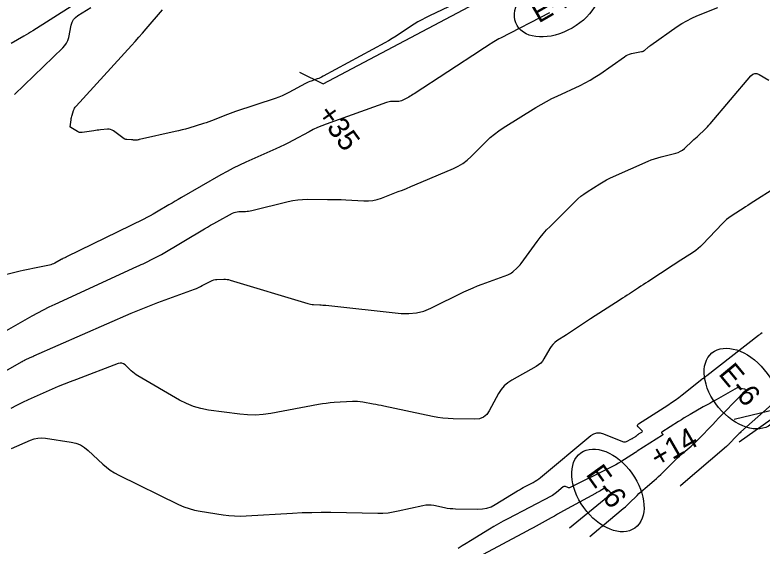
# Model space of a CAD drawing. Extents: x 1005228 to 1008882, y 1883389 to 1885754.
# Drawn here: x 1007873.1 to 1008093.9, y 1884195.8 to 1884352.9 of the extents above; entities that cross this region are included whole.
import ezdxf

# ---------------------------------------------------------------- set-up
doc = ezdxf.new("R2010")
doc.units = 0
for name, color, linetype in [('C-ANNO-NOTE', 7, 'Continuous'), ('R_Erosion', 7, 'Continuous'), ('S_BASELINE', 7, 'Continuous'), ('S_BRIDGE', 7, 'Continuous'), ('TSOBSTACLE', 7, 'Continuous')]:
    doc.layers.add(name, color=color, linetype=linetype)

msp = doc.modelspace()

# ---------------------------------------------------------------- linework, layer by layer
at = {"layer": 'C-ANNO-NOTE'}
for points in [[(1007870.6, 1884259.56), (1007878.17, 1884263.86), (1007879.85, 1884264.79), (1007881.54, 1884265.68), (1007883.26, 1884266.54), (1007885, 1884267.36), (1007909.17, 1884278.46), (1007909.78, 1884278.74), (1007910.38, 1884279.03), (1007910.99, 1884279.32), (1007911.6, 1884279.61), (1007914.01, 1884280.8), (1007914.61, 1884281.1), (1007915.21, 1884281.41), (1007915.79, 1884281.74), (1007916.38, 1884282.07), (1007929.12, 1884289.63), (1007930.02, 1884290.16), (1007930.93, 1884290.68), (1007931.85, 1884291.2), (1007932.77, 1884291.7), (1007937.45, 1884294.23), (1007937.88, 1884294.44), (1007938.33, 1884294.59), (1007938.79, 1884294.68), (1007939.27, 1884294.73), (1007941.21, 1884294.79), (1007941.7, 1884294.81), (1007942.18, 1884294.87), (1007942.65, 1884294.94), (1007943.13, 1884295.05), (1007953.84, 1884297.69), (1007955.25, 1884297.99), (1007956.67, 1884298.2), (1007958.1, 1884298.33), (1007959.54, 1884298.37), (1007965.52, 1884298.34), (1007966.86, 1884298.33), (1007968.2, 1884298.3), (1007969.54, 1884298.25), (1007970.88, 1884298.18), (1007976.26, 1884297.88), (1007977.58, 1884297.88), (1007978.87, 1884298.01), (1007980.15, 1884298.28), (1007981.4, 1884298.69), (1007986.37, 1884300.61), (1007987.61, 1884301.1), (1007988.85, 1884301.59), (1007990.08, 1884302.1), (1007991.31, 1884302.61), (1008002.73, 1884307.46), (1008004.15, 1884308.15), (1008005.5, 1884308.96), (1008006.75, 1884309.9), (1008007.93, 1884310.97), (1008012.44, 1884315.5), (1008013.6, 1884316.59), (1008014.82, 1884317.61), (1008016.09, 1884318.57), (1008017.42, 1884319.45), (1008027.1, 1884325.48), (1008028.64, 1884326.4), (1008030.2, 1884327.28), (1008031.79, 1884328.11), (1008033.41, 1884328.89), (1008040.13, 1884332.02), (1008041.63, 1884332.77), (1008043.1, 1884333.57), (1008044.54, 1884334.44), (1008045.93, 1884335.38), (1008053.22, 1884340.51), (1008053.72, 1884340.82), (1008054.24, 1884341.08), (1008054.78, 1884341.28), (1008055.35, 1884341.42), (1008058.29, 1884342.01), (1008058.56, 1884342.08), (1008058.81, 1884342.18), (1008059.05, 1884342.32), (1008059.27, 1884342.48), (1008060.12, 1884343.21), (1008060.34, 1884343.39), (1008060.56, 1884343.56), (1008060.78, 1884343.73), (1008061.01, 1884343.9), (1008068.86, 1884349.41), (1008070.24, 1884350.33), (1008071.68, 1884351.16), (1008073.15, 1884351.91), (1008074.68, 1884352.58), (1008080.85, 1884355.09)], [(1007889.7, 1884355.35), (1007878.37, 1884348.2), (1007877.72, 1884347.79), (1007877.06, 1884347.39), (1007876.4, 1884347), (1007875.74, 1884346.61), (1007871.97, 1884344.44)], [(1007873.01, 1884329.34), (1007887.28, 1884343.1), (1007887.89, 1884343.78), (1007888.38, 1884344.52), (1007888.75, 1884345.33), (1007889, 1884346.21), (1007889.75, 1884349.85), (1007890.02, 1884350.71), (1007890.43, 1884351.47), (1007890.99, 1884352.12), (1007891.7, 1884352.67), (1007895.53, 1884355.08)], [(1008031.07, 1884353.45), (1008016.57, 1884346.02), (1008016.09, 1884345.77), (1008015.61, 1884345.5), (1008015.13, 1884345.22), (1008014.66, 1884344.94), (1008012.8, 1884343.77), (1008012.34, 1884343.47), (1008011.88, 1884343.18), (1008011.42, 1884342.88), (1008010.96, 1884342.58), (1007991.1, 1884329.54), (1007990.7, 1884329.29), (1007990.3, 1884329.05), (1007989.89, 1884328.81), (1007989.48, 1884328.59), (1007987.71, 1884327.66), (1007987.34, 1884327.49), (1007986.96, 1884327.37), (1007986.56, 1884327.29), (1007986.16, 1884327.26), (1007984.5, 1884327.24), (1007984.09, 1884327.22), (1007983.69, 1884327.16), (1007983.29, 1884327.07), (1007982.9, 1884326.95), (1007965.09, 1884320.57), (1007963.8, 1884320.08), (1007962.53, 1884319.54), (1007961.29, 1884318.96), (1007960.06, 1884318.33), (1007955.19, 1884315.71), (1007953.97, 1884315.06), (1007952.74, 1884314.44), (1007951.49, 1884313.84), (1007950.24, 1884313.27), (1007941.38, 1884309.31), (1007939.5, 1884308.44), (1007937.63, 1884307.52), (1007935.8, 1884306.56), (1007933.98, 1884305.55), (1007922.3, 1884298.85), (1007921.37, 1884298.32), (1007920.45, 1884297.78), (1007919.53, 1884297.24), (1007918.6, 1884296.7), (1007914.92, 1884294.52), (1007914, 1884293.98), (1007913.06, 1884293.46), (1007912.12, 1884292.96), (1007911.16, 1884292.48), (1007888.35, 1884281.31), (1007888.21, 1884281.25), (1007888.08, 1884281.18), (1007887.95, 1884281.12), (1007887.81, 1884281.06), (1007887.28, 1884280.81), (1007887.15, 1884280.75), (1007887.01, 1884280.68), (1007886.88, 1884280.61), (1007886.76, 1884280.54), (1007884.87, 1884279.47), (1007884.51, 1884279.28), (1007884.13, 1884279.13), (1007883.75, 1884279), (1007883.35, 1884278.91), (1007878.42, 1884277.93), (1007877.46, 1884277.74), (1007876.51, 1884277.53), (1007875.56, 1884277.32), (1007874.61, 1884277.09), (1007861.08, 1884273.79)], [(1007852.9, 1884237.72), (1007875.23, 1884250.39), (1007875.31, 1884250.43), (1007875.38, 1884250.48), (1007875.46, 1884250.52), (1007875.54, 1884250.56), (1007875.85, 1884250.74), (1007875.93, 1884250.78), (1007876, 1884250.82), (1007876.08, 1884250.86), (1007876.16, 1884250.9), (1007877.6, 1884251.56), (1007877.87, 1884251.68), (1007878.13, 1884251.8), (1007878.4, 1884251.92), (1007878.67, 1884252.04), (1007907.49, 1884264.66), (1007909.45, 1884265.5), (1007911.41, 1884266.31), (1007913.39, 1884267.08), (1007915.38, 1884267.83), (1007926.15, 1884271.78), (1007926.75, 1884272.01), (1007927.33, 1884272.26), (1007927.9, 1884272.53), (1007928.47, 1884272.82), (1007930.96, 1884274.17), (1007931.4, 1884274.38), (1007931.86, 1884274.53), (1007932.33, 1884274.63), (1007932.82, 1884274.67), (1007934.8, 1884274.73), (1007935.29, 1884274.73), (1007935.78, 1884274.68), (1007936.26, 1884274.6), (1007936.73, 1884274.48), (1007959.63, 1884267.54), (1007960.07, 1884267.43), (1007960.5, 1884267.34), (1007960.95, 1884267.27), (1007961.39, 1884267.24), (1007963.19, 1884267.16), (1007963.64, 1884267.13), (1007964.09, 1884267.1), (1007964.54, 1884267.06), (1007964.99, 1884267.02), (1007987.3, 1884264.63), (1007989.56, 1884264.54), (1007991.78, 1884264.77), (1007993.93, 1884265.31), (1007996.03, 1884266.17), (1008005.8, 1884270.96), (1008007.13, 1884271.6), (1008008.49, 1884272.19), (1008009.85, 1884272.75), (1008011.24, 1884273.28), (1008018.76, 1884276.01), (1008019.16, 1884276.17), (1008019.54, 1884276.38), (1008019.9, 1884276.61), (1008020.24, 1884276.89), (1008021.56, 1884278.05), (1008021.88, 1884278.35), (1008022.18, 1884278.66), (1008022.46, 1884278.99), (1008022.73, 1884279.34), (1008027.43, 1884285.85), (1008028.32, 1884287.04), (1008029.26, 1884288.18), (1008030.24, 1884289.29), (1008031.27, 1884290.35), (1008038.68, 1884297.73), (1008039.5, 1884298.51), (1008040.36, 1884299.23), (1008041.25, 1884299.9), (1008042.19, 1884300.53), (1008046, 1884302.94), (1008046.96, 1884303.53), (1008047.94, 1884304.08), (1008048.94, 1884304.59), (1008049.97, 1884305.06), (1008060.27, 1884309.62), (1008061.2, 1884310), (1008062.14, 1884310.35), (1008063.1, 1884310.65), (1008064.06, 1884310.92), (1008068.47, 1884312.01), (1008069.17, 1884312.23), (1008069.83, 1884312.54), (1008070.44, 1884312.92), (1008071, 1884313.39), (1008073.37, 1884315.6), (1008073.81, 1884316.01), (1008074.26, 1884316.43), (1008074.7, 1884316.84), (1008075.15, 1884317.26), (1008076.93, 1884318.92), (1008077.36, 1884319.34), (1008077.79, 1884319.78), (1008078.2, 1884320.22), (1008078.6, 1884320.68), (1008090.63, 1884334.86), (1008091.18, 1884335.36), (1008091.78, 1884335.59), (1008092.42, 1884335.57), (1008093.1, 1884335.28), (1008095.93, 1884333.62)], [(1008098.77, 1884302.35), (1008090.42, 1884297.01), (1008089.71, 1884296.55), (1008089.01, 1884296.1), (1008088.3, 1884295.64), (1008087.6, 1884295.18), (1008084.79, 1884293.34), (1008084.1, 1884292.86), (1008083.45, 1884292.34), (1008082.82, 1884291.79), (1008082.23, 1884291.2), (1008076.33, 1884285), (1008075.7, 1884284.38), (1008075.04, 1884283.8), (1008074.35, 1884283.25), (1008073.63, 1884282.75), (1008070.66, 1884280.81), (1008069.92, 1884280.32), (1008069.18, 1884279.84), (1008068.44, 1884279.36), (1008067.7, 1884278.87), (1008060.13, 1884273.97), (1008059.45, 1884273.53), (1008058.77, 1884273.08), (1008058.09, 1884272.64), (1008057.41, 1884272.2), (1008054.7, 1884270.42), (1008054.02, 1884269.98), (1008053.34, 1884269.53), (1008052.67, 1884269.09), (1008051.99, 1884268.65), (1008043.26, 1884263), (1008042.66, 1884262.61), (1008042.07, 1884262.22), (1008041.47, 1884261.83), (1008040.87, 1884261.44), (1008038.49, 1884259.87), (1008037.89, 1884259.48), (1008037.29, 1884259.09), (1008036.7, 1884258.7), (1008036.1, 1884258.31), (1008033.29, 1884256.46), (1008032.65, 1884255.99), (1008032.09, 1884255.46), (1008031.59, 1884254.86), (1008031.16, 1884254.2), (1008029.47, 1884251.23), (1008029.02, 1884250.54), (1008028.49, 1884249.93), (1008027.88, 1884249.4), (1008027.19, 1884248.95), (1008019.93, 1884244.87), (1008018.74, 1884244.09), (1008017.69, 1884243.17), (1008016.79, 1884242.11), (1008016.04, 1884240.91), (1008013.3, 1884235.82), (1008012.53, 1884234.7), (1008011.56, 1884233.92), (1008010.4, 1884233.46), (1008009.05, 1884233.33), (1008002.67, 1884233.46), (1008001.13, 1884233.53), (1007999.59, 1884233.67), (1007998.07, 1884233.88), (1007996.55, 1884234.16), (1007982.12, 1884237.18), (1007981.35, 1884237.34), (1007980.58, 1884237.5), (1007979.81, 1884237.65), (1007979.03, 1884237.8), (1007975.94, 1884238.39), (1007975.17, 1884238.51), (1007974.39, 1884238.59), (1007973.61, 1884238.61), (1007972.83, 1884238.59), (1007967.43, 1884238.24), (1007966.27, 1884238.14), (1007965.11, 1884238.02), (1007963.96, 1884237.86), (1007962.82, 1884237.66), (1007948.75, 1884235.06), (1007946.46, 1884234.73), (1007944.17, 1884234.58), (1007941.87, 1884234.61), (1007939.57, 1884234.82), (1007930.35, 1884236.04), (1007928.08, 1884236.46), (1007925.89, 1884237.09), (1007923.77, 1884237.94), (1007921.72, 1884239), (1007909.43, 1884246.17), (1007908.91, 1884246.5), (1007908.4, 1884246.86), (1007907.92, 1884247.24), (1007907.46, 1884247.66), (1007905.66, 1884249.37), (1007905.19, 1884249.72), (1007904.69, 1884249.91), (1007904.16, 1884249.93), (1007903.59, 1884249.79), (1007891.25, 1884245.12), (1007889.45, 1884244.43), (1007887.66, 1884243.71), (1007885.88, 1884242.96), (1007884.1, 1884242.19), (1007877.04, 1884239.07), (1007875.29, 1884238.27), (1007873.55, 1884237.42), (1007871.84, 1884236.53)], [(1008043.01, 1884198.69), (1008045.56, 1884200.79), (1008045.98, 1884201.14), (1008046.41, 1884201.49), (1008046.83, 1884201.84), (1008047.25, 1884202.19), (1008052.32, 1884206.43), (1008052.92, 1884206.94), (1008053.52, 1884207.47), (1008054.11, 1884208.01), (1008054.69, 1884208.56), (1008056.97, 1884210.78), (1008057.55, 1884211.33), (1008058.14, 1884211.87), (1008058.73, 1884212.4), (1008059.33, 1884212.92), (1008062.05, 1884215.25), (1008062.71, 1884215.81), (1008063.34, 1884216.39), (1008063.97, 1884216.98), (1008064.59, 1884217.58), (1008068.38, 1884221.34), (1008068.92, 1884221.87), (1008069.48, 1884222.39), (1008070.04, 1884222.9), (1008070.62, 1884223.4), (1008072.93, 1884225.38), (1008073.5, 1884225.89), (1008074.06, 1884226.4), (1008074.61, 1884226.93), (1008075.15, 1884227.47), (1008079.33, 1884231.79), (1008080.2, 1884232.7), (1008081.08, 1884233.6), (1008081.95, 1884234.5), (1008082.82, 1884235.41), (1008088.93, 1884241.73), (1008089.06, 1884241.89), (1008089.07, 1884242.03), (1008088.99, 1884242.13), (1008088.79, 1884242.19), (1008087.45, 1884242.46), (1008087.38, 1884242.48), (1008087.3, 1884242.5), (1008087.22, 1884242.52), (1008087.15, 1884242.54), (1008086.84, 1884242.64), (1008086.77, 1884242.66), (1008086.7, 1884242.66), (1008086.62, 1884242.65), (1008086.55, 1884242.62), (1008080.33, 1884239.08), (1008079.39, 1884238.55), (1008078.45, 1884238.01), (1008077.51, 1884237.48), (1008076.57, 1884236.95), (1008072.7, 1884234.75), (1008071.82, 1884234.24), (1008070.95, 1884233.72), (1008070.09, 1884233.19), (1008069.23, 1884232.65), (1008064.29, 1884229.48), (1008064.22, 1884229.42), (1008064.19, 1884229.35), (1008064.21, 1884229.28), (1008064.26, 1884229.21), (1008064.56, 1884228.91), (1008064.62, 1884228.84), (1008064.63, 1884228.77), (1008064.6, 1884228.71), (1008064.53, 1884228.65), (1008057.06, 1884223.91), (1008057.01, 1884223.88), (1008056.96, 1884223.85), (1008056.92, 1884223.81), (1008056.87, 1884223.78), (1008056.7, 1884223.64), (1008056.65, 1884223.61), (1008056.61, 1884223.57), (1008056.56, 1884223.54), (1008056.52, 1884223.51), (1008052.19, 1884220.76), (1008051.45, 1884220.3), (1008050.7, 1884219.87), (1008049.93, 1884219.45), (1008049.16, 1884219.05), (1008037.22, 1884213.14), (1008037.05, 1884213.07), (1008036.87, 1884213.05), (1008036.7, 1884213.06), (1008036.52, 1884213.12), (1008035.81, 1884213.41), (1008035.64, 1884213.46), (1008035.47, 1884213.46), (1008035.31, 1884213.41), (1008035.16, 1884213.31), (1008033.19, 1884211.67), (1008032.81, 1884211.37), (1008032.41, 1884211.09), (1008031.99, 1884210.83), (1008031.57, 1884210.59), (1008018.8, 1884203.91), (1008017.41, 1884203.17), (1008016.04, 1884202.41), (1008014.67, 1884201.62), (1008013.32, 1884200.81), (1008007.72, 1884197.38), (1008006.5, 1884196.62), (1008005.28, 1884195.86), (1008004.06, 1884195.09)], [(1008037.05, 1884201.2), (1008047.24, 1884209.59), (1008047.29, 1884209.62), (1008047.33, 1884209.66), (1008047.37, 1884209.69), (1008047.41, 1884209.73), (1008047.58, 1884209.87), (1008047.62, 1884209.9), (1008047.66, 1884209.94), (1008047.7, 1884209.97), (1008047.74, 1884210.01), (1008049.25, 1884211.48), (1008049.28, 1884211.52), (1008049.29, 1884211.55), (1008049.27, 1884211.58), (1008049.24, 1884211.61), (1008049.06, 1884211.72), (1008049.02, 1884211.75), (1008048.98, 1884211.78), (1008048.94, 1884211.81), (1008048.9, 1884211.84), (1008047.84, 1884212.73), (1008047.65, 1884212.85), (1008047.46, 1884212.9), (1008047.26, 1884212.88), (1008047.05, 1884212.78), (1008046.04, 1884212.13), (1008045.93, 1884212.07), (1008045.82, 1884212), (1008045.7, 1884211.94), (1008045.59, 1884211.88), (1008045.12, 1884211.65), (1008045.01, 1884211.59), (1008044.89, 1884211.53), (1008044.78, 1884211.47), (1008044.67, 1884211.41), (1008035.25, 1884206.21), (1008034.34, 1884205.71), (1008033.44, 1884205.22), (1008032.54, 1884204.72), (1008031.64, 1884204.22), (1008028.04, 1884202.24), (1008027.14, 1884201.74), (1008026.23, 1884201.25), (1008025.33, 1884200.75), (1008024.43, 1884200.26), (1008010.06, 1884192.51)]]:
    msp.add_lwpolyline(points, dxfattribs=at)
at = {"layer": 'R_Erosion'}
msp.add_lwpolyline([(1007957.16, 1884335.93), (1007964.25, 1884332.53), (1008055.52, 1884380.91), (1008089.85, 1884389.28)], dxfattribs=at)
for centre, major_axis in [((1008033.4, 1884356.55), (11.86, 6.85)), ((1008087.84, 1884242.39), (8.74, -10.55)), ((1008048.36, 1884212.29), (7.99, -11.12))]:
    msp.add_ellipse(centre, major_axis=major_axis, ratio=0.638788, dxfattribs=at)
at = {"layer": 'S_BRIDGE'}
for points in [[(1008006.67, 1884357.9), (1007995.6, 1884352.61), (1007994.45, 1884352.04), (1007993.32, 1884351.43), (1007992.21, 1884350.78), (1007991.12, 1884350.09), (1007986.81, 1884347.27), (1007985.73, 1884346.57), (1007984.63, 1884345.9), (1007983.52, 1884345.25), (1007982.4, 1884344.62), (1007964.16, 1884334.71), (1007963.74, 1884334.49), (1007963.32, 1884334.29), (1007962.88, 1884334.11), (1007962.44, 1884333.94), (1007960.66, 1884333.31), (1007960.22, 1884333.14), (1007959.79, 1884332.96), (1007959.36, 1884332.76), (1007958.95, 1884332.54), (1007954.02, 1884329.88), (1007953.05, 1884329.39), (1007952.06, 1884328.94), (1007951.05, 1884328.53), (1007950.03, 1884328.16), (1007938.28, 1884324.26), (1007937.48, 1884323.99), (1007936.69, 1884323.7), (1007935.91, 1884323.41), (1007935.13, 1884323.1), (1007932.02, 1884321.84), (1007931.24, 1884321.53), (1007930.45, 1884321.24), (1007929.65, 1884320.97), (1007928.85, 1884320.72), (1007924.5, 1884319.41), (1007923.5, 1884319.12), (1007922.5, 1884318.85), (1007921.49, 1884318.6), (1007920.48, 1884318.36), (1007909.88, 1884316.02), (1007909.8, 1884316), (1007909.71, 1884315.98), (1007909.62, 1884315.96), (1007909.54, 1884315.94), (1007909.19, 1884315.86), (1007909.11, 1884315.84), (1007909.02, 1884315.83), (1007908.93, 1884315.83), (1007908.84, 1884315.83), (1007908.13, 1884315.88), (1007907.98, 1884315.89), (1007907.83, 1884315.9), (1007907.69, 1884315.91), (1007907.54, 1884315.92), (1007906.17, 1884316.01), (1007906.1, 1884316.02), (1007906.04, 1884316.02), (1007905.98, 1884316.04), (1007905.91, 1884316.05), (1007905.66, 1884316.11), (1007905.6, 1884316.13), (1007905.54, 1884316.15), (1007905.48, 1884316.18), (1007905.43, 1884316.22), (1007902.22, 1884318.57), (1007901.8, 1884318.82), (1007901.36, 1884318.99), (1007900.9, 1884319.07), (1007900.41, 1884319.06), (1007898.4, 1884318.87), (1007897.9, 1884318.82), (1007897.4, 1884318.76), (1007896.9, 1884318.7), (1007896.41, 1884318.63), (1007892.94, 1884318.11), (1007892.57, 1884318.09), (1007892.22, 1884318.13), (1007891.87, 1884318.23), (1007891.55, 1884318.4), (1007889.66, 1884319.58), (1007889.64, 1884319.59), (1007889.62, 1884319.61), (1007889.6, 1884319.62), (1007889.57, 1884319.64), (1007889.49, 1884319.7), (1007889.47, 1884319.71), (1007889.46, 1884319.73), (1007889.45, 1884319.76), (1007889.45, 1884319.78), (1007889.69, 1884321.84), (1007889.74, 1884322.19), (1007889.81, 1884322.54), (1007889.89, 1884322.88), (1007889.99, 1884323.22), (1007890.44, 1884324.64), (1007890.57, 1884324.98), (1007890.73, 1884325.3), (1007890.92, 1884325.6), (1007891.15, 1884325.88), (1007907.51, 1884343.83), (1007908.61, 1884345.05), (1007909.7, 1884346.28), (1007910.79, 1884347.51), (1007911.86, 1884348.75), (1007916.73, 1884354.39)], [(1007872.06, 1884224.66), (1007877.67, 1884227.14), (1007878.76, 1884227.54), (1007879.88, 1884227.77), (1007881.02, 1884227.84), (1007882.17, 1884227.74), (1007889.72, 1884226.56), (1007891.12, 1884226.23), (1007892.43, 1884225.72), (1007893.64, 1884225), (1007894.76, 1884224.1), (1007899.03, 1884220.08), (1007900.13, 1884219.12), (1007901.29, 1884218.25), (1007902.52, 1884217.47), (1007903.8, 1884216.78), (1007921.42, 1884208.15), (1007922.98, 1884207.46), (1007924.57, 1884206.89), (1007926.21, 1884206.45), (1007927.88, 1884206.12), (1007934.65, 1884205.07), (1007936.34, 1884204.86), (1007938.04, 1884204.73), (1007939.75, 1884204.7), (1007941.45, 1884204.75), (1007955.16, 1884205.57), (1007957.98, 1884205.71), (1007960.81, 1884205.8), (1007963.63, 1884205.83), (1007966.45, 1884205.81), (1007980.35, 1884205.57), (1007981.87, 1884205.59), (1007983.39, 1884205.7), (1007984.89, 1884205.91), (1007986.38, 1884206.2), (1007993.71, 1884207.87), (1007994.51, 1884208.01), (1007995.3, 1884208.06), (1007996.1, 1884208.02), (1007996.9, 1884207.9), (1008000.1, 1884207.23), (1008000.9, 1884207.08), (1008001.71, 1884206.97), (1008002.52, 1884206.89), (1008003.34, 1884206.86), (1008009.94, 1884206.72), (1008011.29, 1884206.79), (1008012.58, 1884207.04), (1008013.83, 1884207.47), (1008015.03, 1884208.1), (1008021.65, 1884212.15), (1008022.21, 1884212.49), (1008022.78, 1884212.82), (1008023.36, 1884213.14), (1008023.94, 1884213.45), (1008026.27, 1884214.67), (1008026.85, 1884214.99), (1008027.4, 1884215.34), (1008027.94, 1884215.72), (1008028.46, 1884216.13), (1008043.3, 1884228.49), (1008044.18, 1884229.06), (1008045.1, 1884229.35), (1008046.07, 1884229.35), (1008047.08, 1884229.06), (1008052.67, 1884226.74), (1008052.97, 1884226.65), (1008053.27, 1884226.63), (1008053.57, 1884226.67), (1008053.86, 1884226.78), (1008055.35, 1884227.52), (1008055.49, 1884227.59), (1008055.62, 1884227.66), (1008055.74, 1884227.74), (1008055.87, 1884227.81), (1008056.4, 1884228.15), (1008056.51, 1884228.22), (1008056.61, 1884228.3), (1008056.72, 1884228.37), (1008056.82, 1884228.45), (1008057.22, 1884228.77), (1008057.33, 1884228.85), (1008057.43, 1884228.93), (1008057.54, 1884229), (1008057.64, 1884229.07), (1008058.39, 1884229.54), (1008058.51, 1884229.65), (1008058.56, 1884229.76), (1008058.54, 1884229.89), (1008058.44, 1884230.02), (1008057.33, 1884231.12), (1008057.16, 1884231.34), (1008057.12, 1884231.55), (1008057.21, 1884231.75), (1008057.42, 1884231.93), (1008066.11, 1884237.52), (1008067.19, 1884238.23), (1008068.24, 1884238.96), (1008069.28, 1884239.73), (1008070.3, 1884240.51), (1008076.11, 1884245.14), (1008076.23, 1884245.23), (1008076.36, 1884245.33), (1008076.48, 1884245.42), (1008076.61, 1884245.51), (1008077.13, 1884245.86), (1008077.26, 1884245.95), (1008077.39, 1884246.04), (1008077.52, 1884246.13), (1008077.64, 1884246.23), (1008092.87, 1884258.14), (1008093.23, 1884258.42), (1008093.6, 1884258.69), (1008093.98, 1884258.95)], [(1008097.69, 1884238.48), (1008087.68, 1884229.57), (1008087.42, 1884229.33), (1008087.16, 1884229.09), (1008086.9, 1884228.84), (1008086.65, 1884228.58), (1008085.5, 1884227.39), (1008085.33, 1884227.21), (1008085.16, 1884227.04), (1008084.99, 1884226.86), (1008084.81, 1884226.68), (1008084.13, 1884225.97), (1008083.96, 1884225.8), (1008083.78, 1884225.63), (1008083.6, 1884225.46), (1008083.41, 1884225.3), (1008069.95, 1884213.77), (1008069.94, 1884213.77), (1008069.93, 1884213.76), (1008069.92, 1884213.74), (1008069.91, 1884213.73), (1008069.9, 1884213.73), (1008069.69, 1884213.54)]]:
    msp.add_lwpolyline(points, dxfattribs=at)
at = {"layer": 'TSOBSTACLE'}
msp.add_lwpolyline([(1008085.68, 1884233.31), (1008098.35, 1884236.39), (1008099.98, 1884236.68), (1008100.63, 1884236.53), (1008100.32, 1884235.93), (1008099.03, 1884234.9), (1008087.2, 1884226.51)], dxfattribs=at)

# ---------------------------------------------------------------- texts
at = {"layer": 'R_Erosion'}
for s, rotation, p in [('E-11', 30.0083, (1008027.91, 1884350.3)), ('E-6', 309.6346, (1008080.84, 1884246.66)), ('E-6', 305.6982, (1008041.67, 1884217.04))]:
    msp.add_text(s, height=6.25, rotation=rotation, dxfattribs=at).set_placement(p)
at = {"layer": 'S_BASELINE'}
for s, rotation, p in [('+35', 305.6982, (1007962.18, 1884323.58)), ('+14', 29.931, (1008063.2, 1884218.78))]:
    msp.add_text(s, height=6.25, rotation=rotation, dxfattribs=at).set_placement(p)

doc.saveas('drawing.dxf')
